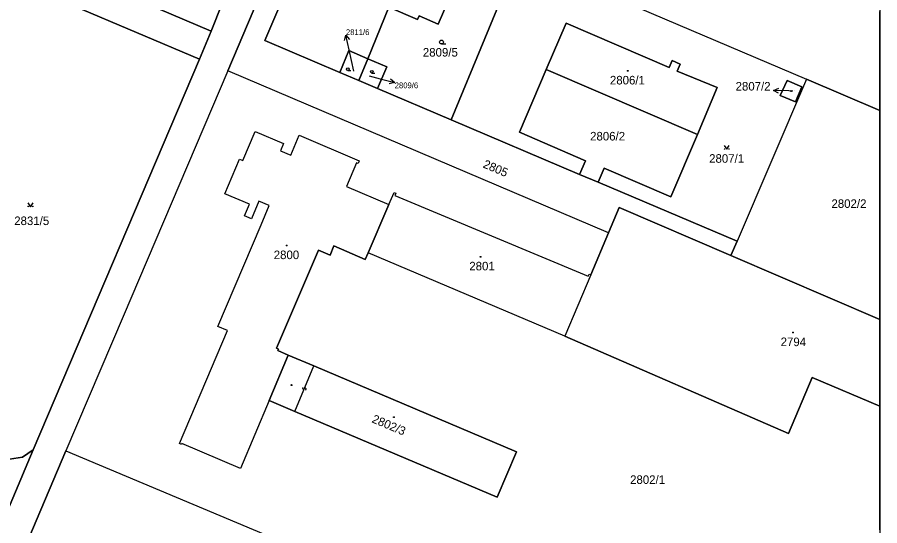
# Model space of a CAD drawing. Extents: x -596024 to -594475, y -1163820 to -1161957.
# Drawn here: x -594646.9 to -594475.5, y -1162407.1 to -1162306 of the extents above; entities that cross this region are included whole.
import ezdxf

# ---------------------------------------------------------------- set-up
doc = ezdxf.new("R2010")
doc.units = 0
for name, color, linetype in [('Level 1', 7, 'Continuous'), ('Level 13', 7, 'Continuous'), ('Level 3', 7, 'Continuous'), ('Level 4', 7, 'Continuous'), ('Level 5', 7, 'Continuous'), ('Level 57', 7, 'Continuous'), ('Level 60', 7, 'Continuous'), ('Vrstva 60', 7, 'Continuous'), ('Vrstva 63', 7, 'Continuous')]:
    doc.layers.add(name, color=color, linetype=linetype)

msp = doc.modelspace()

# ---------------------------------------------------------------- linework, layer by layer
at = {"layer": 'Level 1'}
for p, q in [((-594490.06, -1162318.31), (-594475.47, -1162324.6)), ((-594475.47, -1162366.11), (-594505.06, -1162353.4))]:
    msp.add_line(p, q, dxfattribs=at)
for points in [[(-594605.04, -1162316.67), (-594588.09, -1162276.66)], [(-594582.79, -1162317.01), (-594597.7, -1162310.66), (-594583.9, -1162278.44)], [(-594597.18, -1162280.54), (-594608.33, -1162308.78)], [(-594568.83, -1162293.84), (-594563.33, -1162296.2), (-594562.83, -1162294.95), (-594560.32, -1162296.08), (-594560.75, -1162297.31), (-594559.18, -1162297.98), (-594563.23, -1162307.4), (-594567.04, -1162305.76), (-594567.34, -1162306.45), (-594573.01, -1162304.02)], [(-594560.65, -1162326.44), (-594547.25, -1162293.99)], [(-594635.34, -1162297.28), (-594608.33, -1162308.78)], [(-594648.27, -1162298.38), (-594610.68, -1162314.35)], [(-594531.07, -1162300.87), (-594490.06, -1162318.31)], [(-594573.01, -1162304.02), (-594577.22, -1162314.27)], [(-594511.67, -1162329.31), (-594507.79, -1162319.98), (-594515.72, -1162316.74), (-594515.12, -1162315.36), (-594516.74, -1162314.66), (-594517.33, -1162316.04), (-594537.77, -1162307.18), (-594541.76, -1162316.42)], [(-594608.33, -1162308.78), (-594610.68, -1162314.35)], [(-594582.79, -1162317.01), (-594580.99, -1162312.66), (-594577.22, -1162314.27)], [(-594643.71, -1162392.05), (-594610.68, -1162314.35)], [(-594577.22, -1162314.27), (-594579.01, -1162318.62)], [(-594577.22, -1162314.27), (-594573.46, -1162315.87), (-594575.31, -1162320.2)], [(-594605.04, -1162316.67), (-594625.82, -1162365.52), (-594637.27, -1162392.22)], [(-594529.36, -1162348.89), (-594605.04, -1162316.67)], [(-594582.79, -1162317.01), (-594579.01, -1162318.62)], [(-594541.76, -1162316.42), (-594547.09, -1162328.88), (-594533.97, -1162334.55), (-594535.15, -1162337.3)], [(-594511.67, -1162329.31), (-594541.76, -1162316.42)], [(-594579.01, -1162318.62), (-594575.31, -1162320.2)], [(-594490.06, -1162318.31), (-594503.84, -1162350.54)], [(-594492.22, -1162322.86), (-594495.25, -1162321.61), (-594493.87, -1162318.63), (-594490.93, -1162319.84), (-594492.22, -1162322.86)], [(-594575.31, -1162320.2), (-594560.65, -1162326.44)], [(-594560.65, -1162326.44), (-594535.15, -1162337.3)], [(-594596.84, -1162382.24), (-594602.52, -1162395.77), (-594614.17, -1162390.8), (-594614.23, -1162390.95), (-594614.67, -1162390.76), (-594605.08, -1162368.29), (-594607.02, -1162367.49), (-594598.43, -1162347.31), (-594596.84, -1162343.47), (-594598.89, -1162342.62), (-594600.33, -1162346.1), (-594601.7, -1162345.52), (-594600.74, -1162343.19), (-594605.62, -1162341.11), (-594602.7, -1162334.22), (-594602.04, -1162334.48), (-594599.62, -1162328.77), (-594594, -1162331.14), (-594594.59, -1162332.57), (-594592.55, -1162333.45), (-594590.87, -1162329.45), (-594578.92, -1162334.56), (-594579.13, -1162335.09), (-594579.48, -1162334.95), (-594581.46, -1162339.65), (-594573.02, -1162343.24)], [(-594511.67, -1162329.31), (-594516.98, -1162341.71), (-594530.25, -1162336.03), (-594531.45, -1162338.83)], [(-594535.15, -1162337.3), (-594531.45, -1162338.83)], [(-594503.84, -1162350.54), (-594531.45, -1162338.83)], [(-594573.02, -1162343.24), (-594572.01, -1162340.85), (-594571.68, -1162340.99), (-594571.87, -1162341.45), (-594533.42, -1162357.54), (-594533.23, -1162357.1), (-594532.9, -1162357.24)], [(-594577.14, -1162352.9), (-594573.24, -1162343.75), (-594573.02, -1162343.24)], [(-594529.36, -1162348.89), (-594527.23, -1162343.87), (-594505.06, -1162353.4)], [(-594532.9, -1162357.24), (-594529.36, -1162348.89)], [(-594593.04, -1162373.21), (-594595.09, -1162372.32), (-594594.95, -1162372), (-594595.4, -1162371.81), (-594587, -1162352.33), (-594584.72, -1162353.31), (-594583.95, -1162351.5), (-594577.72, -1162354.17), (-594577.14, -1162352.9)], [(-594505.06, -1162353.4), (-594503.84, -1162350.54)], [(-594538.08, -1162369.46), (-594577.14, -1162352.9)], [(-594532.9, -1162357.24), (-594538.08, -1162369.46)], [(-594475.47, -1162383.37), (-594488.88, -1162377.68), (-594493.6, -1162388.79), (-594538.08, -1162369.46)], [(-594596.84, -1162382.24), (-594593.04, -1162373.21)], [(-594587.92, -1162375.36), (-594593.04, -1162373.21)], [(-594591.72, -1162384.39), (-594551.51, -1162401.47), (-594547.66, -1162392.45), (-594587.92, -1162375.36)], [(-594683.2, -1162380.56), (-594649.29, -1162394.03), (-594645.86, -1162393.52), (-594643.71, -1162392.05)], [(-594596.84, -1162382.24), (-594591.72, -1162384.39)], [(-594637.27, -1162392.22), (-594652.18, -1162427.42), (-594655.04, -1162433.78)], [(-594651.34, -1162409.99), (-594643.71, -1162392.05)], [(-594637.27, -1162392.22), (-594535.51, -1162435.02)]]:
    msp.add_lwpolyline(points, dxfattribs=at)
at = {"layer": 'Level 13'}
for centre, start, end in [((-594589.99, -1162379.81), 104.5504, 336.6484), ((-594589.65, -1162379.95), 284.336, 156.926)]:
    msp.add_arc(centre, 0.184, start, end, dxfattribs=at)
at = {"layer": 'Level 3'}
msp.add_lwpolyline([(-594591.72, -1162384.39), (-594587.92, -1162375.36)], dxfattribs=at)
at = {"layer": 'Level 5'}
for p, q in [((-594562.57, -1162311.33), (-594561.7, -1162311.33)), ((-594581.19, -1162316.61), (-594580.59, -1162316.61)), ((-594576.41, -1162317.12), (-594575.82, -1162317.12))]:
    msp.add_line(p, q, dxfattribs=at)
for points in [[(-594506.37, -1162331.51), (-594505.87, -1162332.26), (-594505.37, -1162331.51)], [(-594644.76, -1162342.95), (-594644.26, -1162343.7), (-594643.76, -1162342.95)]]:
    msp.add_lwpolyline(points, dxfattribs=at)
for centre, radius in [((-594562.57, -1162310.95), 0.375), ((-594581.19, -1162316.35), 0.255), ((-594576.41, -1162316.86), 0.255), ((-594525.56, -1162316.69), 0.09), ((-594525.56, -1162316.69), 0.0521), ((-594493.08, -1162320.7), 0.09), ((-594493.08, -1162320.7), 0.0521), ((-594506.32, -1162332.21), 0.05), ((-594505.42, -1162332.21), 0.05), ((-594644.71, -1162343.65), 0.05), ((-594643.81, -1162343.65), 0.05), ((-594593.35, -1162351.42), 0.09), ((-594593.35, -1162351.42), 0.0521), ((-594554.81, -1162353.66), 0.09), ((-594554.81, -1162353.66), 0.0521), ((-594492.71, -1162368.72), 0.09), ((-594492.71, -1162368.72), 0.0521), ((-594592.37, -1162379.16), 0.09), ((-594592.37, -1162379.16), 0.0521), ((-594572.03, -1162385.55), 0.09), ((-594572.03, -1162385.55), 0.0521)]:
    msp.add_circle(centre, radius, dxfattribs=at)
at = {"layer": 'Level 57'}
for p, q in [((-594580.94, -1162312.5), (-594581.56, -1162309.57)), ((-594580.02, -1162316.78), (-594580.94, -1162312.5)), ((-594576.92, -1162317.71), (-594574.78, -1162318.26)), ((-594574.78, -1162318.26), (-594571.87, -1162319)), ((-594493.56, -1162320.68), (-594496.56, -1162320.6)), ((-594492.73, -1162320.7), (-594493.56, -1162320.68))]:
    msp.add_line(p, q, dxfattribs=at)
for points in [[(-594581.84, -1162310.65), (-594581.56, -1162309.57), (-594580.87, -1162310.44)], [(-594572.71, -1162318.27), (-594571.87, -1162319), (-594572.96, -1162319.24)], [(-594495.57, -1162321.13), (-594496.56, -1162320.6), (-594495.55, -1162320.13)]]:
    msp.add_lwpolyline(points, dxfattribs=at)
at = {"layer": 'Level 60'}
msp.add_lwpolyline([(-594660.41, -1162245.9), (-594639.76, -1162254.61), (-594598.82, -1162272.04), (-594597.12, -1162274.15), (-594597.22, -1162276.99), (-594598.57, -1162280), (-594597.18, -1162280.54), (-594608.33, -1162308.78), (-594635.34, -1162297.28), (-594633.95, -1162294.03), (-594631.8, -1162289.03), (-594634.89, -1162287.71), (-594637.99, -1162286.39), (-594641.09, -1162285.07), (-594644.21, -1162283.74), (-594647.33, -1162282.42)], dxfattribs=at)
for points in [[(-594693.16, -1162272.69), (-594686.42, -1162275.54), (-594650.76, -1162290.72), (-594635.34, -1162297.28), (-594608.33, -1162308.78), (-594610.68, -1162314.35), (-594648.27, -1162298.38), (-594695.58, -1162278.29)], [(-594675.58, -1162445.23), (-594673.97, -1162440.12), (-594671.23, -1162441.24), (-594667.96, -1162441.13), (-594665.34, -1162439.76), (-594663.46, -1162437.42), (-594660.9, -1162432.59), (-594651.34, -1162409.99), (-594643.71, -1162392.05), (-594610.68, -1162314.35), (-594608.33, -1162308.78), (-594597.18, -1162280.54), (-594594.51, -1162273.87), (-594593.93, -1162274.12), (-594588.09, -1162276.66), (-594605.04, -1162316.67), (-594625.82, -1162365.52), (-594637.27, -1162392.22), (-594652.18, -1162427.42), (-594655.04, -1162433.78), (-594664.15, -1162454.04), (-594676.67, -1162448.71)], [(-594535.15, -1162337.3), (-594531.45, -1162338.83), (-594503.84, -1162350.54), (-594505.06, -1162353.4), (-594527.23, -1162343.87), (-594529.36, -1162348.89), (-594605.04, -1162316.67), (-594588.09, -1162276.66), (-594587.91, -1162276.73), (-594583.9, -1162278.44), (-594597.7, -1162310.66), (-594582.79, -1162317.01), (-594579.01, -1162318.62), (-594575.31, -1162320.2), (-594560.65, -1162326.44)], [(-594582.79, -1162317.01), (-594597.7, -1162310.66), (-594583.9, -1162278.44), (-594565.6, -1162286.2), (-594568.83, -1162293.84), (-594578.38, -1162289.73), (-594578.45, -1162289.89), (-594580.66, -1162288.93), (-594582.11, -1162292.32), (-594579.9, -1162293.27), (-594582.43, -1162299.17), (-594578.57, -1162300.83), (-594578.87, -1162301.51), (-594573.01, -1162304.02), (-594577.22, -1162314.27), (-594580.99, -1162312.66)], [(-594560.65, -1162326.44), (-594575.31, -1162320.2), (-594573.46, -1162315.87), (-594577.22, -1162314.27), (-594573.01, -1162304.02), (-594567.34, -1162306.45), (-594567.04, -1162305.76), (-594563.23, -1162307.4), (-594559.18, -1162297.98), (-594560.75, -1162297.31), (-594560.32, -1162296.08), (-594562.83, -1162294.95), (-594563.33, -1162296.2), (-594568.83, -1162293.84), (-594565.6, -1162286.2), (-594547.25, -1162293.99)], [(-594573.01, -1162304.02), (-594568.83, -1162293.84), (-594563.33, -1162296.2), (-594562.83, -1162294.95), (-594560.32, -1162296.08), (-594560.75, -1162297.31), (-594559.18, -1162297.98), (-594563.23, -1162307.4), (-594567.04, -1162305.76), (-594567.34, -1162306.45)], [(-594541.76, -1162316.42), (-594547.09, -1162328.88), (-594533.97, -1162334.55), (-594535.15, -1162337.3), (-594560.65, -1162326.44), (-594547.25, -1162293.99), (-594531.07, -1162300.87), (-594490.06, -1162318.31), (-594503.84, -1162350.54), (-594531.45, -1162338.83), (-594530.25, -1162336.03), (-594516.98, -1162341.71), (-594511.67, -1162329.31), (-594507.79, -1162319.98), (-594515.72, -1162316.74), (-594515.12, -1162315.36), (-594516.74, -1162314.66), (-594517.33, -1162316.04), (-594537.77, -1162307.18)], [(-594648.27, -1162298.38), (-594610.68, -1162314.35), (-594643.71, -1162392.05), (-594645.86, -1162393.52), (-594649.29, -1162394.03), (-594683.2, -1162380.56)], [(-594515.72, -1162316.74), (-594507.79, -1162319.98), (-594511.67, -1162329.31), (-594541.76, -1162316.42), (-594537.77, -1162307.18), (-594517.33, -1162316.04), (-594516.74, -1162314.66), (-594515.12, -1162315.36)], [(-594579.01, -1162318.62), (-594582.79, -1162317.01), (-594580.99, -1162312.66), (-594577.22, -1162314.27)], [(-594575.31, -1162320.2), (-594579.01, -1162318.62), (-594577.22, -1162314.27), (-594573.46, -1162315.87)], [(-594547.09, -1162328.88), (-594541.76, -1162316.42), (-594511.67, -1162329.31), (-594516.98, -1162341.71), (-594530.25, -1162336.03), (-594531.45, -1162338.83), (-594535.15, -1162337.3), (-594533.97, -1162334.55)], [(-594495.25, -1162321.61), (-594492.22, -1162322.86), (-594490.93, -1162319.84), (-594493.87, -1162318.63)], [(-594492.22, -1162322.86), (-594495.25, -1162321.61), (-594493.87, -1162318.63), (-594490.93, -1162319.84)], [(-594594.95, -1162372), (-594595.09, -1162372.32), (-594593.04, -1162373.21), (-594596.84, -1162382.24), (-594602.52, -1162395.77), (-594614.17, -1162390.8), (-594614.23, -1162390.95), (-594614.67, -1162390.76), (-594605.08, -1162368.29), (-594607.02, -1162367.49), (-594598.43, -1162347.31), (-594596.84, -1162343.47), (-594598.89, -1162342.62), (-594600.33, -1162346.1), (-594601.7, -1162345.52), (-594600.74, -1162343.19), (-594605.62, -1162341.11), (-594602.7, -1162334.22), (-594602.04, -1162334.48), (-594599.62, -1162328.77), (-594594, -1162331.14), (-594594.59, -1162332.57), (-594592.55, -1162333.45), (-594590.87, -1162329.45), (-594578.92, -1162334.56), (-594579.13, -1162335.09), (-594579.48, -1162334.95), (-594581.46, -1162339.65), (-594573.02, -1162343.24), (-594573.24, -1162343.75), (-594577.14, -1162352.9), (-594577.72, -1162354.17), (-594583.95, -1162351.5), (-594584.72, -1162353.31), (-594587, -1162352.33), (-594595.4, -1162371.81)], [(-594538.08, -1162369.46), (-594577.14, -1162352.9), (-594573.24, -1162343.75), (-594573.02, -1162343.24), (-594572.01, -1162340.85), (-594571.68, -1162340.99), (-594571.87, -1162341.45), (-594533.42, -1162357.54), (-594533.23, -1162357.1), (-594532.9, -1162357.24)], [(-594667.43, -1162402.94), (-594676.97, -1162399.54), (-594736.66, -1162375.16), (-594737.51, -1162375.26), (-594734.83, -1162369.04), (-594699.4, -1162383.25), (-594696.5, -1162383.23), (-594694.11, -1162382.09), (-594692.6, -1162380.36), (-594691.28, -1162377.35), (-594683.2, -1162380.56), (-594649.29, -1162394.03), (-594645.86, -1162393.52), (-594643.71, -1162392.05), (-594651.34, -1162409.99)], [(-594547.66, -1162392.45), (-594551.51, -1162401.47), (-594591.72, -1162384.39), (-594596.84, -1162382.24), (-594593.04, -1162373.21), (-594587.92, -1162375.36)], [(-594555.05, -1162477.07), (-594600.78, -1162456.89), (-594588.79, -1162428.45), (-594594.5, -1162426.08), (-594594.41, -1162425.87), (-594595.27, -1162425.51), (-594626.69, -1162412.19), (-594633.35, -1162409.55), (-594643.19, -1162432.83), (-594639.91, -1162434.25), (-594641.97, -1162439.22), (-594655.04, -1162433.78), (-594652.18, -1162427.42), (-594637.27, -1162392.22), (-594535.51, -1162435.02), (-594545.95, -1162456.27)]]:
    msp.add_lwpolyline(points, close=True, dxfattribs=at)
at = {"layer": 'Vrstva 60'}
for points in [[(-594531.07, -1162300.87), (-594490.06, -1162318.31), (-594475.47, -1162324.6), (-594475.47, -1162304.87)], [(-594475.47, -1162407.92), (-594475.47, -1162383.37), (-594488.88, -1162377.68), (-594493.6, -1162388.79), (-594538.08, -1162369.46), (-594577.14, -1162352.9), (-594577.72, -1162354.17), (-594583.95, -1162351.5), (-594584.72, -1162353.31), (-594587, -1162352.33), (-594595.4, -1162371.81), (-594594.95, -1162372), (-594595.09, -1162372.32), (-594593.04, -1162373.21), (-594587.92, -1162375.36), (-594547.66, -1162392.45), (-594551.51, -1162401.47), (-594591.72, -1162384.39), (-594596.84, -1162382.24), (-594602.52, -1162395.77), (-594614.17, -1162390.8), (-594614.23, -1162390.95), (-594614.67, -1162390.76), (-594605.08, -1162368.29), (-594607.02, -1162367.49), (-594598.43, -1162347.31), (-594596.84, -1162343.47), (-594598.89, -1162342.62), (-594600.33, -1162346.1), (-594601.7, -1162345.52), (-594600.74, -1162343.19), (-594605.62, -1162341.11), (-594602.7, -1162334.22), (-594602.04, -1162334.48), (-594599.62, -1162328.77), (-594594, -1162331.14), (-594594.59, -1162332.57), (-594592.55, -1162333.45), (-594590.87, -1162329.45), (-594578.92, -1162334.56), (-594579.13, -1162335.09), (-594579.48, -1162334.95), (-594581.46, -1162339.65), (-594573.02, -1162343.24), (-594572.01, -1162340.85), (-594571.68, -1162340.99), (-594571.87, -1162341.45), (-594533.42, -1162357.54), (-594533.23, -1162357.1), (-594532.9, -1162357.24), (-594529.36, -1162348.89), (-594605.04, -1162316.67), (-594625.82, -1162365.52), (-594637.27, -1162392.22), (-594535.51, -1162435.02)]]:
    msp.add_lwpolyline(points, dxfattribs=at)
for points in [[(-594475.47, -1162366.11), (-594475.47, -1162324.6), (-594490.06, -1162318.31), (-594503.84, -1162350.54), (-594505.06, -1162353.4)], [(-594475.47, -1162383.37), (-594475.47, -1162366.11), (-594505.06, -1162353.4), (-594527.23, -1162343.87), (-594529.36, -1162348.89), (-594532.9, -1162357.24), (-594538.08, -1162369.46), (-594493.6, -1162388.79), (-594488.88, -1162377.68)]]:
    msp.add_lwpolyline(points, close=True, dxfattribs=at)
at = {"layer": 'Vrstva 63'}
msp.add_lwpolyline([(-594475.47, -1163820.23), (-596024.42, -1163820.23), (-596024.42, -1161956.88), (-594475.47, -1161956.88)], close=True, dxfattribs=at)

# ---------------------------------------------------------------- texts
at = {"layer": 'Level 4'}
for s, height, p in [('2809/5', 1.7, (-594566.28, -1162313.85)), ('2811/6', 0.1, (-594580.02, -1162316.78)), ('2809/6', 0.1, (-594576.92, -1162317.71)), ('2806/1', 1.7, (-594529.1, -1162319.39)), ('2807/2', 0.1, (-594492.73, -1162320.7)), ('2806/2', 1.7, (-594533.04, -1162330.53)), ('2807/1', 1.7, (-594509.38, -1162334.96)), ('2802/2', 1.7, (-594485.07, -1162343.94)), ('2831/5', 1.7, (-594647.5, -1162347.35)), ('2800', 1.7, (-594595.92, -1162354.12)), ('2801', 1.7, (-594557.05, -1162356.36)), ('2794', 1.7, (-594495.17, -1162371.42)), ('2802/1', 1.7, (-594525.09, -1162398.82))]:
    msp.add_text(s, height=height, dxfattribs=at).set_placement(p)
for s, rotation, p in [('2805', 336.9828, (-594554.47, -1162335.85)), ('2802/3', 337.2102, (-594576.56, -1162386.53))]:
    msp.add_text(s, height=1.7, rotation=rotation, dxfattribs=at).set_placement(p)
at = {"layer": 'Level 57'}
for s, height, p in [('2811/6', 1.14, (-594581.57, -1162309.57)), ('2809/6', 1.14, (-594571.87, -1162320.14)), ('2807/2', 1.7, (-594504.12, -1162320.6))]:
    msp.add_text(s, height=height, dxfattribs=at).set_placement(p)

doc.saveas('drawing.dxf')
